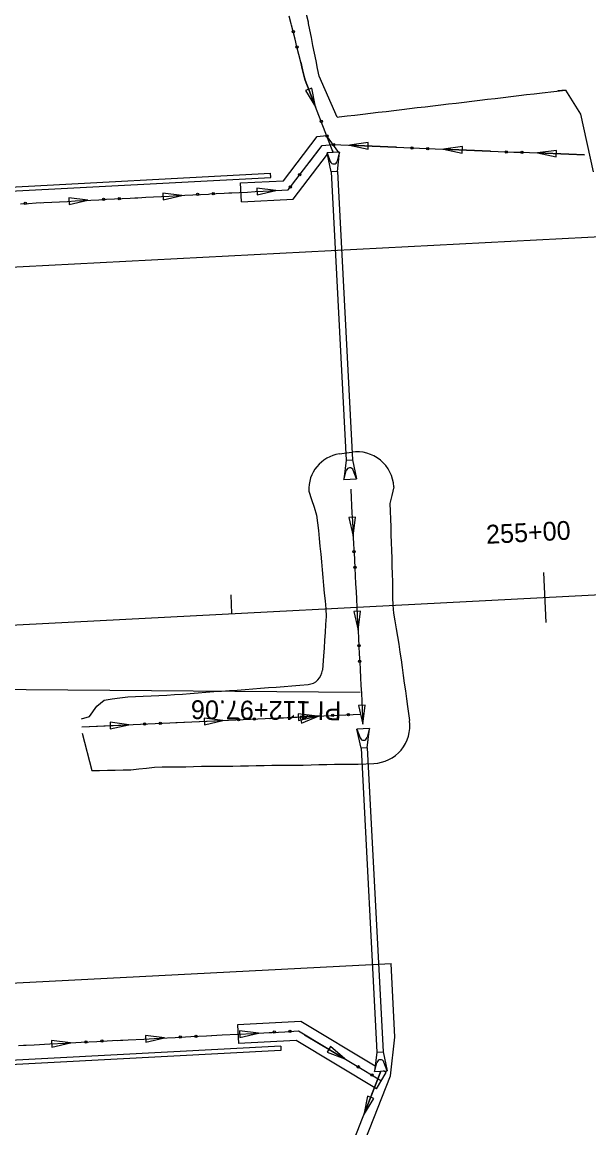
# Model space of a CAD drawing. Extents: x 1311167 to 1314552, y 2087587 to 2090602.
# Drawn here: x 1314085.4 to 1314266.2, y 2089153.5 to 2089506 of the extents above; entities that cross this region are included whole.
import ezdxf

# ---------------------------------------------------------------- set-up
doc = ezdxf.new("R2010")
doc.units = 0
for name, color, linetype in [('MOT_Proposed Road_1A', 7, 'Continuous'), ('R_Guardrail', 7, 'Continuous'), ('R_Proposed Road', 7, 'Continuous'), ('R_Shoulder', 7, 'Continuous'), ('S_DITCHLINE', 7, 'Continuous'), ('S_EDGE_BITUMINOUS', 7, 'Continuous'), ('S_EDGE_CONCRETE', 7, 'Continuous'), ('S_EDGE_PAVEMENT', 7, 'Continuous'), ('S_WALL', 7, 'Continuous')]:
    doc.layers.add(name, color=color, linetype=linetype)

msp = doc.modelspace()

# ---------------------------------------------------------------- linework, layer by layer
at = {"layer": 'MOT_Proposed Road_1A'}
for p, q in [((1314186.42, 2089464.51), (1314182.42, 2089469.84)), ((1314155.02, 2089454.75), (1314168.71, 2089455.46)), ((1314155.33, 2089448.76), (1314155.02, 2089454.75)), ((1314155.33, 2089448.76), (1314171.78, 2089449.61)), ((1314154.11, 2089186.35), (1314154.43, 2089180.35)), ((1314198.01, 2089173.17), (1314174.28, 2089187.39)), ((1314198.44, 2089165.92), (1314172.76, 2089181.3)), ((1314198.44, 2089165.92), (1314201.52, 2089171.07)), ((1314201.52, 2089171.07), (1314200.61, 2089171.61))]:
    msp.add_line(p, q, dxfattribs=at)
for points in [[(1314168.71, 2089455.46), (1314179.5, 2089469.52), (1314182.42, 2089469.84)], [(1314171.78, 2089449.61), (1314182.74, 2089463.88)], [(1314174.28, 2089187.39), (1314154.11, 2089186.35)], [(1314172.76, 2089181.3), (1314154.43, 2089180.35)]]:
    msp.add_lwpolyline(points, dxfattribs=at)
at = {"layer": 'R_Guardrail'}
msp.add_lwpolyline([(1314073.23, 2089293.36), (1314193.23, 2089292.37)], dxfattribs=at)
at = {"layer": 'R_Proposed Road'}
msp.add_line((1313503.08, 2089283.78), (1314551.67, 2089338.12), dxfattribs=at)
at = {"layer": 'R_Shoulder'}
for points in [[(1314251.66, 2089330.59), (1314252.49, 2089314.61)], [(1314151.9, 2089323.41), (1314152.21, 2089317.42)]]:
    msp.add_lwpolyline(points, dxfattribs=at)
at = {"layer": 'S_DITCHLINE'}
for p, q in [((1314177.77, 2089485.01), (1314175.8, 2089484.24)), ((1314178.96, 2089479.03), (1314177.77, 2089485.01)), ((1314175.8, 2089484.24), (1314178.96, 2089479.03)), ((1314195.81, 2089467.62), (1314189.77, 2089466.82)), ((1314195.72, 2089465.5), (1314195.81, 2089467.62)), ((1314189.77, 2089466.82), (1314195.72, 2089465.5)), ((1314225.82, 2089466.33), (1314219.78, 2089465.53)), ((1314219.78, 2089465.53), (1314225.73, 2089464.21)), ((1314225.73, 2089464.21), (1314225.82, 2089466.33)), ((1314255.83, 2089465.15), (1314249.8, 2089464.32)), ((1314249.8, 2089464.32), (1314255.75, 2089463.04)), ((1314255.75, 2089463.04), (1314255.83, 2089465.15)), ((1314166.34, 2089452.33), (1314160.29, 2089453.08)), ((1314160.29, 2089453.08), (1314160.4, 2089450.97)), ((1314166.34, 2089452.33), (1314160.29, 2089453.08)), ((1314160.29, 2089453.08), (1314160.4, 2089450.97)), ((1314106.34, 2089449.23), (1314100.3, 2089449.97)), ((1314100.3, 2089449.97), (1314100.4, 2089447.86)), ((1314106.34, 2089449.23), (1314100.3, 2089449.97)), ((1314100.3, 2089449.97), (1314100.4, 2089447.86)), ((1314136.34, 2089450.78), (1314130.29, 2089451.53)), ((1314130.29, 2089451.53), (1314130.4, 2089449.41)), ((1314136.34, 2089450.78), (1314130.29, 2089451.53)), ((1314130.29, 2089451.53), (1314130.4, 2089449.41)), ((1314130.4, 2089449.41), (1314136.34, 2089450.78)), ((1314130.4, 2089449.41), (1314136.34, 2089450.78)), ((1314160.4, 2089450.97), (1314166.34, 2089452.33)), ((1314160.4, 2089450.97), (1314166.34, 2089452.33)), ((1314100.4, 2089447.86), (1314106.34, 2089449.23)), ((1314100.4, 2089447.86), (1314106.34, 2089449.23)), ((1314191.72, 2089348.23), (1314189.61, 2089348.12)), ((1314189.61, 2089348.12), (1314190.98, 2089342.18)), ((1314190.98, 2089342.18), (1314191.72, 2089348.23)), ((1314193.28, 2089318.23), (1314191.17, 2089318.12)), ((1314191.17, 2089318.12), (1314192.53, 2089312.19)), ((1314192.53, 2089312.19), (1314193.28, 2089318.23)), ((1314194.83, 2089288.23), (1314192.72, 2089288.13)), ((1314192.72, 2089288.13), (1314194.09, 2089282.19)), ((1314194.09, 2089282.19), (1314194.83, 2089288.23)), ((1314130.8, 2089182.13), (1314124.75, 2089182.88)), ((1314124.75, 2089182.88), (1314124.86, 2089180.77)), ((1314124.86, 2089180.77), (1314130.8, 2089182.13)), ((1314160.79, 2089183.69), (1314154.75, 2089184.43)), ((1314154.75, 2089184.43), (1314154.86, 2089182.32)), ((1314154.86, 2089182.32), (1314160.79, 2089183.69)), ((1314173.52, 2089184.35), (1314199.98, 2089168.5)), ((1314100.8, 2089180.58), (1314094.75, 2089181.32)), ((1314094.75, 2089181.32), (1314094.86, 2089179.21)), ((1314094.86, 2089179.21), (1314100.8, 2089180.58)), ((1314183.75, 2089179.45), (1314182.66, 2089177.64)), ((1314188.36, 2089175.46), (1314183.75, 2089179.45)), ((1314182.66, 2089177.64), (1314188.36, 2089175.46)), ((1314195.56, 2089163.57), (1314194.37, 2089157.6)), ((1314195.56, 2089163.57), (1314194.37, 2089157.6)), ((1314194.37, 2089157.6), (1314197.53, 2089162.8)), ((1314194.37, 2089157.6), (1314197.53, 2089162.8)), ((1314197.53, 2089162.8), (1314195.56, 2089163.57)), ((1314197.53, 2089162.8), (1314195.56, 2089163.57))]:
    msp.add_line(p, q, dxfattribs=at)
for points in [[(1314184.64, 2089464.42), (1314175.65, 2089487.54), (1314175.46, 2089488.32), (1314174.86, 2089490.78), (1314174.26, 2089493.23), (1314173.65, 2089495.68), (1314173.05, 2089498.14), (1314172.44, 2089500.59), (1314171.83, 2089503.04), (1314171.32, 2089505.06), (1314171.22, 2089505.5), (1314170.6, 2089507.95)], [(1314174.25, 2089493.28), (1314174.26, 2089493.24)], [(1314174.26, 2089493.24), (1314174.26, 2089493.23), (1314174.86, 2089490.78), (1314175.46, 2089488.32), (1314175.65, 2089487.54), (1314178.96, 2089479.03)], [(1314170.25, 2089452.54), (1314181.1, 2089466.67), (1314184.51, 2089467.05), (1314184.52, 2089467.05)], [(1314177.02, 2089461.36), (1314181.1, 2089466.67), (1314184.51, 2089467.05), (1314184.52, 2089467.05)], [(1314177.02, 2089461.36), (1314181.1, 2089466.67), (1314184.51, 2089467.05), (1314184.52, 2089467.05)], [(1314184.52, 2089467.05), (1314187.02, 2089466.94), (1314189.53, 2089466.83), (1314192.03, 2089466.72), (1314194.54, 2089466.61), (1314197.05, 2089466.51), (1314199.56, 2089466.4), (1314202.07, 2089466.29), (1314204.58, 2089466.18), (1314207.09, 2089466.07), (1314209.6, 2089465.96), (1314212.11, 2089465.86), (1314214.62, 2089465.75), (1314217.12, 2089465.64), (1314219.63, 2089465.53), (1314222.14, 2089465.43), (1314224.65, 2089465.32), (1314227.16, 2089465.21), (1314229.67, 2089465.1), (1314232.18, 2089464.99), (1314234.69, 2089464.9), (1314237.19, 2089464.8), (1314239.7, 2089464.71), (1314242.21, 2089464.61), (1314244.72, 2089464.52), (1314247.23, 2089464.42), (1314249.74, 2089464.32), (1314252.24, 2089464.23), (1314257.26, 2089464.04), (1314259.77, 2089463.94), (1314264.79, 2089463.75)], [(1314184.4, 2089465.05), (1314184.41, 2089465.02)], [(1314184.41, 2089465.01), (1314184.64, 2089464.42)], [(1314204.76, 2089466.17), (1314204.58, 2089466.18), (1314202.07, 2089466.29), (1314199.56, 2089466.4), (1314197.05, 2089466.51), (1314194.54, 2089466.61), (1314192.03, 2089466.72), (1314189.77, 2089466.82)], [(1314204.8, 2089466.17), (1314204.76, 2089466.17)], [(1314234.77, 2089464.89), (1314234.69, 2089464.9), (1314232.18, 2089464.99), (1314229.67, 2089465.1), (1314227.16, 2089465.21), (1314224.65, 2089465.32), (1314222.14, 2089465.43), (1314219.78, 2089465.53)], [(1314234.81, 2089464.89), (1314234.77, 2089464.89)], [(1314264.79, 2089463.75), (1314259.77, 2089463.94), (1314257.26, 2089464.04), (1314252.24, 2089464.23), (1314249.8, 2089464.32)], [(1314177, 2089461.33), (1314177.02, 2089461.36)], [(1314177, 2089461.33), (1314177.02, 2089461.36)], [(1314084.85, 2089448.11), (1314087.35, 2089448.24), (1314089.85, 2089448.37), (1314092.34, 2089448.5), (1314094.84, 2089448.63), (1314097.34, 2089448.76), (1314099.83, 2089448.89), (1314102.33, 2089449.02), (1314104.83, 2089449.15), (1314107.32, 2089449.28), (1314109.82, 2089449.41), (1314112.32, 2089449.53), (1314114.81, 2089449.66), (1314117.31, 2089449.79), (1314119.81, 2089449.92), (1314122.3, 2089450.05), (1314124.8, 2089450.18), (1314127.3, 2089450.31), (1314129.79, 2089450.44), (1314132.29, 2089450.57), (1314134.79, 2089450.7), (1314137.28, 2089450.83), (1314139.78, 2089450.96), (1314142.28, 2089451.09), (1314144.77, 2089451.22), (1314145.27, 2089451.24), (1314147.27, 2089451.35), (1314149.77, 2089451.48), (1314152.26, 2089451.61), (1314154.76, 2089451.73), (1314157.26, 2089451.86), (1314159.75, 2089451.99), (1314162.25, 2089452.12), (1314170.25, 2089452.54)], [(1314121.32, 2089450), (1314121.36, 2089450)], [(1314121.32, 2089450), (1314121.36, 2089450)], [(1314121.36, 2089450), (1314122.3, 2089450.05), (1314124.8, 2089450.18), (1314127.3, 2089450.31), (1314129.79, 2089450.44), (1314132.29, 2089450.57), (1314134.79, 2089450.7), (1314136.34, 2089450.78)], [(1314121.36, 2089450), (1314122.3, 2089450.05), (1314124.8, 2089450.18), (1314127.3, 2089450.31), (1314129.79, 2089450.44), (1314132.29, 2089450.57), (1314134.79, 2089450.7), (1314136.34, 2089450.78)], [(1314151.32, 2089451.56), (1314151.36, 2089451.56)], [(1314151.32, 2089451.56), (1314151.36, 2089451.56)], [(1314151.36, 2089451.56), (1314152.26, 2089451.61), (1314154.76, 2089451.73), (1314157.26, 2089451.86), (1314159.75, 2089451.99), (1314162.25, 2089452.12), (1314166.34, 2089452.33)], [(1314151.36, 2089451.56), (1314152.26, 2089451.61), (1314154.76, 2089451.73), (1314157.26, 2089451.86), (1314159.75, 2089451.99), (1314162.25, 2089452.12), (1314166.34, 2089452.33)], [(1314091.32, 2089448.45), (1314091.36, 2089448.45)], [(1314091.32, 2089448.45), (1314091.36, 2089448.45)], [(1314091.36, 2089448.45), (1314092.34, 2089448.5), (1314094.84, 2089448.63), (1314097.34, 2089448.76), (1314099.83, 2089448.89), (1314102.33, 2089449.02), (1314104.83, 2089449.15), (1314106.34, 2089449.23)], [(1314091.36, 2089448.45), (1314092.34, 2089448.5), (1314094.84, 2089448.63), (1314097.34, 2089448.76), (1314099.83, 2089448.89), (1314102.33, 2089449.02), (1314104.83, 2089449.15), (1314106.34, 2089449.23)], [(1314190.2, 2089357.16), (1314190.21, 2089356.94), (1314190.34, 2089354.45), (1314190.47, 2089351.95), (1314190.6, 2089349.45), (1314190.73, 2089346.96), (1314190.86, 2089344.46), (1314190.99, 2089341.96), (1314191.12, 2089339.47), (1314191.25, 2089336.97), (1314191.38, 2089334.47), (1314191.51, 2089331.98), (1314191.64, 2089329.48), (1314191.77, 2089326.98), (1314191.9, 2089324.49), (1314192.03, 2089321.99), (1314192.15, 2089319.49), (1314192.28, 2089317), (1314192.41, 2089314.5), (1314192.54, 2089312), (1314192.67, 2089309.51), (1314192.8, 2089307.01), (1314192.93, 2089304.51), (1314193.06, 2089302.02), (1314193.19, 2089299.52), (1314193.32, 2089297.02), (1314193.45, 2089294.53), (1314193.58, 2089292.03), (1314193.71, 2089289.53), (1314193.84, 2089287.04), (1314193.97, 2089284.54), (1314194.03, 2089283.37)], [(1314190.2, 2089357.16), (1314190.21, 2089356.94), (1314190.34, 2089354.45), (1314190.47, 2089351.95), (1314190.6, 2089349.45), (1314190.73, 2089346.96), (1314190.86, 2089344.46), (1314190.98, 2089342.18)], [(1314191.75, 2089327.2), (1314191.76, 2089327.17)], [(1314191.76, 2089327.17), (1314191.77, 2089326.98), (1314191.9, 2089324.49), (1314192.03, 2089321.99), (1314192.15, 2089319.49), (1314192.28, 2089317), (1314192.41, 2089314.5), (1314192.53, 2089312.19)], [(1314193.31, 2089297.21), (1314193.31, 2089297.17)], [(1314193.31, 2089297.17), (1314193.32, 2089297.02), (1314193.45, 2089294.53), (1314193.58, 2089292.03), (1314193.71, 2089289.53), (1314193.84, 2089287.04), (1314193.97, 2089284.54), (1314194.03, 2089283.37)], [(1314084.24, 2089179.72), (1314089.24, 2089179.98), (1314094.23, 2089180.24), (1314099.22, 2089180.5), (1314104.22, 2089180.76), (1314109.21, 2089181.01), (1314114.2, 2089181.27), (1314119.2, 2089181.53), (1314124.19, 2089181.79), (1314129.18, 2089182.05), (1314134.18, 2089182.31), (1314139.17, 2089182.57), (1314144.16, 2089182.83), (1314149.16, 2089183.08), (1314154.15, 2089183.34), (1314159.14, 2089183.6), (1314164.14, 2089183.86), (1314165.14, 2089183.91), (1314167.13, 2089184.02), (1314169.13, 2089184.12), (1314173.52, 2089184.35)], [(1314115.82, 2089181.36), (1314119.2, 2089181.53), (1314124.19, 2089181.79), (1314129.18, 2089182.05), (1314130.8, 2089182.13)], [(1314145.78, 2089182.91), (1314145.81, 2089182.91)], [(1314145.81, 2089182.91), (1314149.16, 2089183.08), (1314154.15, 2089183.34), (1314159.14, 2089183.6), (1314160.79, 2089183.69)], [(1314175.46, 2089183.19), (1314175.49, 2089183.17)], [(1314175.49, 2089183.17), (1314188.36, 2089175.46)], [(1314085.78, 2089179.8), (1314085.82, 2089179.8)], [(1314085.82, 2089179.8), (1314089.24, 2089179.98), (1314094.23, 2089180.24), (1314099.22, 2089180.5), (1314100.8, 2089180.58)], [(1314115.78, 2089181.35), (1314115.81, 2089181.36)], [(1314184.7, 2089132.83), (1314199.82, 2089171.57)], [(1314184.7, 2089132.83), (1314199.82, 2089171.57)], [(1314199.82, 2089171.57), (1314194.37, 2089157.6)], [(1314199.82, 2089171.57), (1314194.37, 2089157.6)]]:
    msp.add_lwpolyline(points, dxfattribs=at)
for centre in [(1314171.88, 2089502.99), (1314173.09, 2089498.12), (1314180.81, 2089474.38), (1314182.62, 2089469.71), (1314184.77, 2089467), (1314209.77, 2089465.92), (1314214.78, 2089465.7), (1314239.79, 2089464.67), (1314244.79, 2089464.48), (1314173.93, 2089457.4), (1314173.93, 2089457.4), (1314170.88, 2089453.42), (1314170.88, 2089453.42), (1314111.34, 2089449.52), (1314111.34, 2089449.52), (1314116.34, 2089449.78), (1314116.34, 2089449.78), (1314141.34, 2089451.08), (1314141.34, 2089451.08), (1314146.34, 2089451.33), (1314146.34, 2089451.33), (1314086.34, 2089448.23), (1314086.34, 2089448.23), (1314191.27, 2089337.19), (1314191.53, 2089332.18), (1314192.83, 2089307.19), (1314193.09, 2089302.18), (1314110.8, 2089181.13), (1314135.79, 2089182.43), (1314140.8, 2089182.69), (1314165.79, 2089183.98), (1314170.79, 2089184.24), (1314105.79, 2089180.87), (1314192.67, 2089172.92), (1314196.97, 2089170.34)]:
    msp.add_circle(centre, 0.375, dxfattribs=at)
at = {"layer": 'S_EDGE_BITUMINOUS'}
for p, q in [((1314186.64, 2089464.52), (1314182.65, 2089464.31)), ((1314183.96, 2089458.25), (1314182.65, 2089464.31)), ((1314182.65, 2089464.31), (1314183.68, 2089461.56)), ((1314186.64, 2089464.52), (1314185.9, 2089461.68)), ((1314185.96, 2089458.36), (1314186.64, 2089464.52)), ((1314185.96, 2089458.36), (1314183.96, 2089458.25)), ((1314183.96, 2089458.25), (1314188.72, 2089366.38)), ((1314185.96, 2089458.36), (1314190.72, 2089366.48)), ((1314188.72, 2089366.38), (1314188.04, 2089360.21)), ((1314188.72, 2089366.38), (1314190.72, 2089366.48)), ((1314190.72, 2089366.48), (1314192.04, 2089360.42)), ((1314188.04, 2089360.21), (1314188.79, 2089363.06)), ((1314192.04, 2089360.42), (1314191, 2089363.17)), ((1314188.04, 2089360.21), (1314192.04, 2089360.42)), ((1314196.16, 2089280.77), (1314192.17, 2089280.56)), ((1314193.48, 2089274.5), (1314192.17, 2089280.56)), ((1314192.17, 2089280.56), (1314193.2, 2089277.81)), ((1314196.16, 2089280.77), (1314195.42, 2089277.93)), ((1314195.48, 2089274.6), (1314196.16, 2089280.77)), ((1314195.48, 2089274.6), (1314193.48, 2089274.5)), ((1314193.48, 2089274.5), (1314198.5, 2089177.63)), ((1314195.48, 2089274.6), (1314200.5, 2089177.73)), ((1314198.5, 2089177.63), (1314197.82, 2089171.47)), ((1314198.5, 2089177.63), (1314200.5, 2089177.73)), ((1314200.5, 2089177.73), (1314201.82, 2089171.67)), ((1314201.82, 2089171.67), (1314200.78, 2089174.42)), ((1314197.82, 2089171.47), (1314198.57, 2089174.31)), ((1314197.82, 2089171.47), (1314201.82, 2089171.67))]:
    msp.add_line(p, q, dxfattribs=at)
for centre, start, end in [((1314184.77, 2089461.97), 200.4966, 345.4367), ((1314189.91, 2089362.77), 20.4966, 165.4367), ((1314194.29, 2089278.21), 200.4966, 345.4367), ((1314199.69, 2089174.02), 20.4966, 165.4367)]:
    msp.add_arc(centre, 1.17, start, end, dxfattribs=at)
at = {"layer": 'S_EDGE_CONCRETE'}
for p, q in [((1314186.56, 2089368.33), (1314190.5, 2089368.91)), ((1314104.45, 2089281.32), (1314193.33, 2089285.33)), ((1314149.44, 2089283.35), (1314143.4, 2089284.14)), ((1314143.4, 2089284.14), (1314143.5, 2089282.02)), ((1314179.45, 2089284.71), (1314173.41, 2089285.49)), ((1314173.41, 2089285.49), (1314173.51, 2089283.38)), ((1314173.51, 2089283.38), (1314179.45, 2089284.71)), ((1314180.13, 2089284.86), (1314174.05, 2089284.58)), ((1314174.05, 2089284.58), (1314174.51, 2089282.52)), ((1314174.51, 2089282.52), (1314180.13, 2089284.86)), ((1314119.44, 2089282), (1314113.4, 2089282.78)), ((1314113.4, 2089282.78), (1314113.49, 2089280.67)), ((1314113.49, 2089280.67), (1314119.44, 2089282)), ((1314143.5, 2089282.02), (1314149.44, 2089283.35))]:
    msp.add_line(p, q, dxfattribs=at)
for points in [[(1314185.86, 2089475.78), (1314180.11, 2089488.77), (1314179.63, 2089491.24), (1314179.14, 2089493.7), (1314178.65, 2089496.17), (1314178.16, 2089498.63), (1314177.67, 2089501.09), (1314177.17, 2089503.56), (1314176.76, 2089505.59), (1314176.68, 2089506.02), (1314176.04, 2089508.47)], [(1314185.86, 2089475.78), (1314186.56, 2089475.81), (1314189.04, 2089476.1), (1314191.53, 2089476.4), (1314194.02, 2089476.7), (1314196.51, 2089476.99), (1314199, 2089477.29), (1314201.48, 2089477.58), (1314203.97, 2089477.88), (1314206.46, 2089478.17), (1314208.95, 2089478.47), (1314211.44, 2089478.77), (1314213.93, 2089479.06), (1314216.41, 2089479.36), (1314218.9, 2089479.65), (1314221.39, 2089479.95), (1314223.88, 2089480.24), (1314226.37, 2089480.54), (1314228.85, 2089480.84), (1314231.34, 2089481.13), (1314233.83, 2089481.43), (1314236.32, 2089481.72), (1314238.81, 2089482.02), (1314241.29, 2089482.31), (1314243.78, 2089482.61), (1314246.27, 2089482.91), (1314248.76, 2089483.2), (1314251.25, 2089483.5), (1314258.71, 2089484.38), (1314263.47, 2089476.71), (1314267.57, 2089458.31)], [(1314258.71, 2089484.38), (1314256.22, 2089484.09)], [(1314203.95, 2089357.88), (1314203.3, 2089355.12), (1314202.71, 2089352.58), (1314202.78, 2089350.08), (1314202.86, 2089347.58), (1314202.94, 2089345.09), (1314203.02, 2089342.59), (1314203.1, 2089340.09), (1314203.19, 2089337.59), (1314203.27, 2089335.09), (1314203.35, 2089332.59), (1314203.43, 2089330.09), (1314203.51, 2089327.59), (1314203.54, 2089325.09), (1314203.56, 2089322.59), (1314203.58, 2089320.08), (1314203.79, 2089317.59), (1314204.25, 2089315.11), (1314204.71, 2089312.63), (1314205.17, 2089310.15), (1314205.55, 2089307.67), (1314205.9, 2089305.18), (1314206.24, 2089302.7), (1314206.59, 2089300.21), (1314206.93, 2089297.73), (1314207.28, 2089295.24), (1314207.62, 2089292.76), (1314207.97, 2089290.27), (1314208.31, 2089287.79), (1314208.94, 2089283.3)], [(1314176.83, 2089356.47), (1314177.7, 2089353.79), (1314178.5, 2089351.33), (1314179.3, 2089348.87), (1314179.64, 2089346.38), (1314179.89, 2089343.89), (1314180.13, 2089341.4), (1314180.38, 2089338.91), (1314180.62, 2089336.42), (1314180.87, 2089333.93), (1314181.1, 2089331.44), (1314181.32, 2089328.94), (1314181.54, 2089326.45), (1314181.77, 2089323.96), (1314181.99, 2089321.47), (1314182.21, 2089318.98), (1314182.33, 2089316.48), (1314182.16, 2089313.97), (1314182, 2089311.46), (1314181.84, 2089308.94), (1314181.68, 2089306.43), (1314181.52, 2089303.92), (1314181.16, 2089299.43)], [(1314104.34, 2089283.89), (1314106.81, 2089284.62), (1314109.16, 2089287.92), (1314111.58, 2089289.83), (1314114.06, 2089290.28), (1314116.55, 2089290.62), (1314119.04, 2089290.85), (1314121.53, 2089290.96), (1314124.03, 2089291.06), (1314126.53, 2089291.17), (1314129.03, 2089291.27), (1314131.52, 2089291.43), (1314134.02, 2089291.59), (1314136.51, 2089291.75), (1314139.01, 2089291.92), (1314141.5, 2089292.14), (1314143.99, 2089292.37), (1314146.49, 2089292.56), (1314148.98, 2089292.72), (1314151.48, 2089292.88), (1314153.97, 2089293.05), (1314156.47, 2089293.26), (1314158.96, 2089293.49), (1314161.45, 2089293.69), (1314163.95, 2089293.85), (1314166.44, 2089294.02), (1314168.94, 2089294.18), (1314171.43, 2089294.39), (1314173.92, 2089294.62), (1314176.59, 2089294.84)], [(1314164.43, 2089284.03), (1314164.47, 2089284.03)], [(1314164.47, 2089284.03), (1314179.45, 2089284.71)], [(1314179.45, 2089284.71), (1314173.41, 2089285.49), (1314173.51, 2089283.38), (1314179.45, 2089284.71)], [(1314104.45, 2089281.32), (1314119.44, 2089282)], [(1314134.42, 2089282.67), (1314134.46, 2089282.68)], [(1314134.46, 2089282.68), (1314149.44, 2089283.35)], [(1314104.54, 2089279.32), (1314107.58, 2089267.36), (1314110.08, 2089267.45), (1314112.58, 2089267.5), (1314115.08, 2089267.56), (1314117.58, 2089267.62), (1314120.08, 2089267.67), (1314122.58, 2089267.89), (1314125.06, 2089268.2), (1314127.55, 2089268.52), (1314130.05, 2089268.59), (1314132.55, 2089268.58), (1314135.06, 2089268.58), (1314137.56, 2089268.63), (1314140.06, 2089268.68), (1314142.56, 2089268.74), (1314145.06, 2089268.79), (1314147.56, 2089268.84), (1314150.06, 2089268.83), (1314152.56, 2089268.82), (1314155.07, 2089268.86), (1314157.57, 2089268.91), (1314160.07, 2089268.96), (1314162.57, 2089269.02), (1314165.07, 2089269.07), (1314167.57, 2089269.11), (1314170.07, 2089269.11), (1314172.57, 2089269.11), (1314175.07, 2089269.16), (1314177.57, 2089269.22), (1314180.07, 2089269.27), (1314182.57, 2089269.33), (1314185.07, 2089269.38), (1314187.57, 2089269.42), (1314190.08, 2089269.42), (1314192.58, 2089269.45), (1314197.54, 2089269.65)], [(1314188.15, 2089132.51), (1314202.91, 2089170.09), (1314204.27, 2089182.4), (1314203.05, 2089205.9)]]:
    msp.add_lwpolyline(points, dxfattribs=at)
for centre in [(1314154.44, 2089283.61), (1314159.45, 2089283.84), (1314184.45, 2089284.97), (1314189.46, 2089285.19), (1314124.44, 2089282.26), (1314129.44, 2089282.49)]:
    msp.add_circle(centre, 0.375, dxfattribs=at)
for centre, radius, start, end in [((1314188.21, 2089357.06), 11.39, 98.299, 182.9667), ((1314192.2, 2089357.27), 11.76, 2.9667, 98.299), ((1314176.18, 2089299.82), 5, 274.7301, 355.424), ((1314197.05, 2089281.64), 12, 272.3118, 7.9083)]:
    msp.add_arc(centre, radius, start, end, dxfattribs=at)
at = {"layer": 'S_EDGE_PAVEMENT'}
for p, q in [((1313871.68, 2089417.04), (1314480.86, 2089448.61)), ((1313553.62, 2089172.25), (1314203.05, 2089205.9))]:
    msp.add_line(p, q, dxfattribs=at)
at = {"layer": 'S_WALL'}
for p, q in [((1313957.93, 2089446.98), (1314164.64, 2089457.82)), ((1313958, 2089445.64), (1314164.71, 2089456.49)), ((1314164.71, 2089456.49), (1314164.64, 2089457.82)), ((1314167.86, 2089179.49), (1313961.65, 2089168.61)), ((1314167.93, 2089178.15), (1313961.72, 2089167.28)), ((1314167.86, 2089179.49), (1314167.93, 2089178.15))]:
    msp.add_line(p, q, dxfattribs=at)

# ---------------------------------------------------------------- texts
at = {"layer": 'R_Guardrail'}
msp.add_text('PI 112+97.06', height=6, rotation=179.5313, dxfattribs=at).set_placement((1314187.21, 2089289.42))
at = {"layer": 'R_Shoulder'}
msp.add_text('255+00', height=6, rotation=2.9667, dxfattribs=at).set_placement((1314233.52, 2089339.66))

doc.saveas('drawing.dxf')
